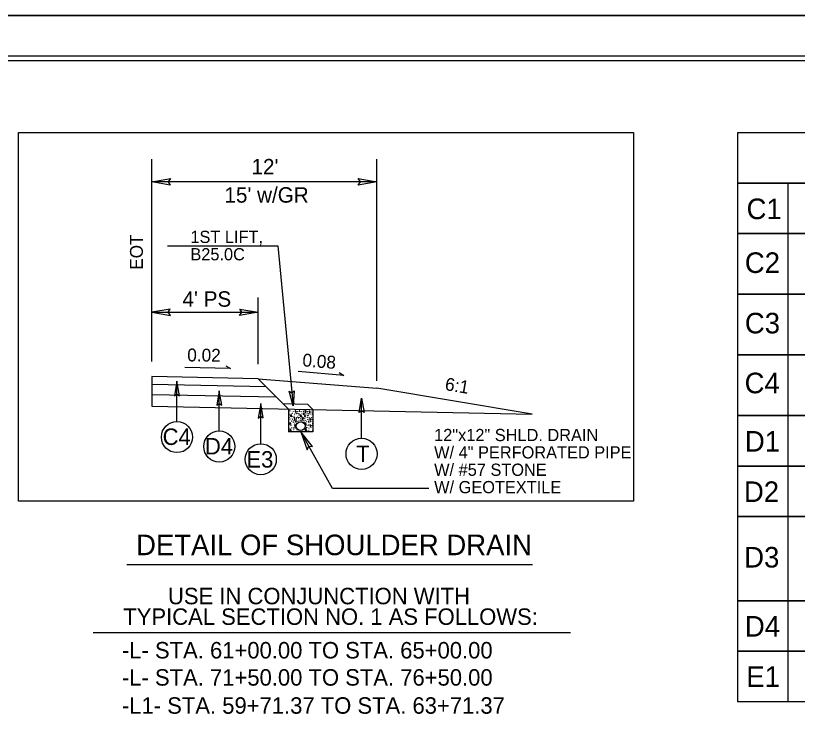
# Model space of a CAD drawing. Extents: x 573813 to 575363, y -54752 to -53123.
# Drawn here: x 574713.4 to 574799.8, y -53200.6 to -53122.8 of the extents above; entities that cross this region are included whole.
import ezdxf

# ---------------------------------------------------------------- set-up
doc = ezdxf.new("R2010")
doc.units = 0
for name, color, linetype in [('Old_Level_1', 7, 'Continuous'), ('Old_Level_11', 7, 'Continuous'), ('Old_Level_2', 7, 'Continuous'), ('Prop Pavement Schedule Description CELL', 7, 'Continuous'), ('Sheet Cutting Line CELL', 7, 'Continuous'), ('Sheet Plot Border Inside CELL', 7, 'Continuous'), ('Sheet Plot Border Outside CELL', 7, 'Continuous'), ('Sheet Typical CELL', 7, 'Continuous'), ('Typical Curb CELL', 7, 'Continuous'), ('Typical ID Circle CELL', 7, 'Continuous'), ('Typical Terminator CELL', 7, 'Continuous')]:
    doc.layers.add(name, color=color, linetype=linetype)

msp = doc.modelspace()

# ---------------------------------------------------------------- linework, layer by layer
at = {"layer": 'Old_Level_1'}
for p, q in [((574737.156, -53161.805), (574732.098, -53161.7)), ((574736.61, -53161.532), (574737.156, -53161.805)), ((574740.21, -53162.963), (574728.439, -53162.718)), ((574740.21, -53162.963), (574743.555, -53166.307)), ((574740.21, -53162.963), (574753.308, -53164.005)), ((574749.664, -53162.571), (574744.624, -53162.133)), ((574749.137, -53162.263), (574749.664, -53162.571)), ((574741.078, -53163.831), (574728.439, -53163.568)), ((574728.439, -53164.673), (574742.206, -53164.959)), ((574770.476, -53166.867), (574753.308, -53164.005)), ((574728.439, -53165.993), (574770.476, -53166.867)), ((574742.937, -53165.69), (574745.642, -53165.746)), ((574745.642, -53165.746), (574746.259, -53166.363))]:
    msp.add_line(p, q, dxfattribs=at)
at = {"layer": 'Old_Level_11'}
for p, q in [((574728.439, -53161.032), (574728.439, -53138.705)), ((574753.308, -53163.186), (574753.308, -53138.706)), ((574753.308, -53141.192), (574728.439, -53141.192)), ((574730.18, -53148.279), (574742.38, -53148.279)), ((574742.38, -53148.279), (574744.058, -53165.931)), ((574740.21, -53161.343), (574740.21, -53153.987)), ((574728.439, -53155.6), (574740.21, -53155.6)), ((574748.424, -53175.085), (574744.907, -53168.827)), ((574759.059, -53175.085), (574748.424, -53175.085)), ((574725.687, -53183.454), (574770.532, -53183.454)), ((574721.951, -53190.973), (574774.709, -53190.973))]:
    msp.add_line(p, q, dxfattribs=at)
for points in [[(574730.486, -53141.544), (574728.439, -53141.192), (574730.497, -53140.828), (574730.236, -53141.191)], [(574751.261, -53140.839), (574753.308, -53141.192), (574751.25, -53141.556), (574751.511, -53141.192)], [(574730.486, -53155.248), (574728.439, -53155.6), (574730.497, -53155.964), (574730.236, -53155.6)], [(574738.163, -53155.248), (574740.21, -53155.6), (574738.152, -53155.964), (574738.413, -53155.6)], [(574744.184, -53164.275), (574744.058, -53165.931), (574743.613, -53164.32), (574743.922, -53164.5)], [(574746.217, -53170.439), (574744.907, -53168.827), (574745.598, -53170.8), (574745.787, -53170.393)]]:
    msp.add_lwpolyline(points, close=True, dxfattribs=at)
at = {"layer": 'Old_Level_2'}
for p, q in [((574728.439, -53162.718), (574728.439, -53165.993)), ((574743.555, -53166.307), (574743.555, -53168.827)), ((574746.259, -53166.363), (574746.259, -53168.827)), ((574746.259, -53168.827), (574743.555, -53168.827))]:
    msp.add_line(p, q, dxfattribs=at)
msp.add_circle((574744.898, -53168.18), 0.485, dxfattribs=at)
at = {"layer": 'Prop Pavement Schedule Description CELL'}
for points in [[(574713.697, -53135.756), (574781.699, -53135.756), (574781.699, -53176.482), (574713.697, -53176.482)], [(574793.203, -53135.756), (574941.304, -53135.756), (574941.304, -53141.35), (574793.203, -53141.35)]]:
    msp.add_lwpolyline(points, close=True, dxfattribs=at)
for points in [[(574798.785, -53146.919), (574793.203, -53146.919), (574793.203, -53141.35), (574867.256, -53141.35), (574867.256, -53146.919), (574798.785, -53146.919), (574798.785, -53141.338)], [(574798.785, -53153.617), (574793.203, -53153.617), (574793.203, -53146.919), (574867.257, -53146.919), (574867.257, -53153.617), (574798.785, -53153.617), (574798.785, -53146.919)], [(574798.785, -53160.315), (574793.203, -53160.315), (574793.203, -53153.617), (574867.257, -53153.617), (574867.257, -53160.315), (574798.785, -53160.315), (574798.785, -53153.617)], [(574798.785, -53167.012), (574793.203, -53167.012), (574793.203, -53160.315), (574867.257, -53160.315), (574867.257, -53167.012), (574798.785, -53167.012), (574798.785, -53160.315)], [(574798.785, -53172.594), (574793.203, -53172.594), (574793.203, -53167.012), (574867.251, -53167.012), (574867.251, -53172.594), (574798.785, -53172.594), (574798.785, -53167.012)], [(574798.785, -53178.175), (574793.203, -53178.175), (574793.203, -53172.594), (574867.251, -53172.594), (574867.251, -53178.16), (574798.785, -53178.16), (574798.785, -53172.594)], [(574798.785, -53187.465), (574793.204, -53187.465), (574793.203, -53178.175), (574867.248, -53178.155), (574867.25, -53187.465), (574798.784, -53187.483), (574798.781, -53178.171)], [(574798.785, -53193.046), (574793.204, -53193.046), (574793.204, -53187.465), (574867.25, -53187.465), (574867.25, -53193.046), (574798.785, -53193.046), (574798.785, -53187.465)], [(574798.785, -53198.628), (574793.204, -53198.628), (574793.204, -53193.046), (574867.25, -53193.046), (574867.25, -53198.628), (574798.785, -53198.628), (574798.785, -53193.046)]]:
    msp.add_lwpolyline(points, dxfattribs=at)
at = {"layer": 'Sheet Cutting Line CELL'}
msp.add_line((574669.731, -53122.834), (575006.712, -53122.834), dxfattribs=at)
at = {"layer": 'Sheet Plot Border Inside CELL'}
msp.add_lwpolyline([(575005.811, -53127.327), (574672.332, -53127.327), (574672.332, -53338.46), (575005.811, -53338.46)], close=True, dxfattribs=at)
at = {"layer": 'Sheet Plot Border Outside CELL'}
msp.add_line((575006.712, -53122.834), (574669.731, -53122.834), dxfattribs=at)
msp.add_lwpolyline([(575006.712, -53122.834), (574669.731, -53122.834), (574669.731, -53342.952), (575006.712, -53342.952)], close=True, dxfattribs=at)
at = {"layer": 'Sheet Typical CELL'}
msp.add_lwpolyline([(575003.31, -53127.837), (574703.149, -53127.837), (574703.149, -53337.95), (575003.31, -53337.95)], close=True, dxfattribs=at)
at = {"layer": 'Typical Curb CELL'}
for p, q in [((574743.883, -53166.95), (574743.771, -53166.972)), ((574743.771, -53166.972), (574743.828, -53167.141)), ((574743.828, -53167.141), (574743.883, -53166.95)), ((574744.284, -53166.458), (574744.349, -53166.69)), ((574744.412, -53166.549), (574744.284, -53166.458)), ((574744.349, -53166.69), (574744.412, -53166.549)), ((574744.967, -53166.965), (574744.855, -53166.987)), ((574744.855, -53166.987), (574744.912, -53167.157)), ((574744.912, -53167.157), (574744.967, -53166.965)), ((574745.039, -53167.241), (574745.103, -53167.473)), ((574745.166, -53167.332), (574745.039, -53167.241)), ((574745.425, -53166.993), (574745.312, -53167.015)), ((574745.312, -53167.015), (574745.369, -53167.185)), ((574745.368, -53166.474), (574745.433, -53166.705)), ((574745.496, -53166.565), (574745.368, -53166.474)), ((574745.369, -53167.185), (574745.425, -53166.993)), ((574745.433, -53166.705), (574745.496, -53166.565)), ((574745.826, -53166.502), (574745.891, -53166.733)), ((574745.954, -53166.593), (574745.826, -53166.502)), ((574745.891, -53166.733), (574745.954, -53166.593)), ((574743.789, -53167.817), (574743.676, -53167.838)), ((574743.676, -53167.838), (574743.733, -53168.008)), ((574743.733, -53168.008), (574743.789, -53167.817)), ((574744.19, -53167.325), (574744.254, -53167.556)), ((574744.318, -53167.416), (574744.19, -53167.325)), ((574744.212, -53168.053), (574744.277, -53168.284)), ((574744.34, -53168.144), (574744.212, -53168.053)), ((574744.254, -53167.556), (574744.318, -53167.416)), ((574744.277, -53168.284), (574744.34, -53168.144)), ((574745.103, -53167.473), (574745.166, -53167.332)), ((574745.479, -53167.839), (574745.366, -53167.861)), ((574745.366, -53167.861), (574745.424, -53168.031)), ((574745.424, -53168.031), (574745.479, -53167.839)), ((574745.88, -53167.348), (574745.945, -53167.579)), ((574746.008, -53167.439), (574745.88, -53167.348)), ((574745.903, -53168.007), (574745.967, -53168.239)), ((574746.031, -53168.098), (574745.903, -53168.007)), ((574745.945, -53167.579), (574746.008, -53167.439)), ((574745.967, -53168.239), (574746.031, -53168.098)), ((574743.811, -53168.545), (574743.699, -53168.566)), ((574743.699, -53168.566), (574743.756, -53168.736)), ((574743.756, -53168.736), (574743.811, -53168.545)), ((574745.502, -53168.499), (574745.389, -53168.521)), ((574745.389, -53168.521), (574745.446, -53168.69)), ((574745.446, -53168.69), (574745.502, -53168.499))]:
    msp.add_line(p, q, dxfattribs=at)
for centre in [(574744.299, -53166.374), (574745.383, -53166.389), (574745.841, -53166.417), (574743.634, -53166.961), (574743.634, -53167.201), (574743.659, -53166.838), (574743.67, -53166.476), (574743.694, -53166.521), (574743.877, -53166.528), (574743.933, -53167.106), (574743.968, -53166.775), (574744.109, -53166.549), (574744.158, -53167.169), (574744.18, -53166.754), (574744.201, -53166.902), (574744.204, -53167.24), (574744.412, -53166.803), (574744.424, -53167.259), (574744.56, -53166.578), (574744.567, -53167.197), (574744.588, -53167.007), (574744.637, -53166.796), (574744.718, -53166.977), (574744.718, -53167.216), (574744.743, -53166.853), (574744.754, -53166.491), (574744.778, -53166.536), (574744.961, -53166.544), (574745.017, -53167.121), (574745.052, -53166.79), (574745.053, -53167.157), (574745.176, -53167.005), (574745.176, -53167.244), (574745.193, -53166.565), (574745.2, -53166.881), (574745.211, -53166.519), (574745.236, -53166.565), (574745.242, -53167.184), (574745.264, -53166.769), (574745.285, -53166.917), (574745.418, -53166.572), (574745.475, -53167.149), (574745.496, -53166.818), (574745.51, -53166.818), (574745.644, -53166.593), (574745.651, -53166.593), (574745.651, -53167.212), (574745.672, -53167.022), (574745.7, -53167.212), (574745.721, -53166.797), (574745.721, -53166.811), (574745.742, -53166.945), (574745.895, -53167.263), (574745.954, -53166.846), (574746.101, -53166.621), (574746.108, -53167.24), (574746.129, -53167.05), (574746.179, -53166.839), (574743.575, -53167.342), (574743.598, -53168.07), (574743.599, -53167.388), (574743.622, -53168.116), (574743.782, -53167.395), (574743.805, -53168.123), (574743.838, -53167.972), (574743.874, -53167.641), (574744.014, -53167.416), (574744.037, -53168.144), (574744.064, -53168.035), (574744.085, -53167.62), (574744.106, -53167.768), (574744.227, -53167.968), (574744.317, -53167.669), (574744.388, -53167.745), (574744.388, -53167.984), (574744.413, -53167.621), (574744.448, -53167.304), (574744.465, -53167.444), (574744.493, -53167.873), (574744.542, -53167.662), (574744.631, -53167.311), (574744.723, -53167.558), (574744.863, -53167.332), (574744.934, -53167.537), (574744.955, -53167.685), (574745.166, -53167.586), (574745.254, -53167.727), (574745.265, -53167.365), (574745.29, -53167.41), (574745.314, -53167.361), (574745.342, -53167.79), (574745.391, -53167.579), (574745.472, -53167.418), (574745.495, -53168.077), (574745.529, -53167.995), (574745.564, -53167.664), (574745.705, -53167.439), (574745.727, -53168.098), (574745.754, -53168.058), (574745.775, -53167.643), (574745.796, -53167.791), (574745.918, -53167.923), (574746.008, -53167.692), (574746.155, -53167.467), (574746.162, -53168.086), (574746.178, -53168.127), (574746.184, -53167.896), (574746.233, -53167.685), (574743.587, -53168.432), (574743.861, -53168.7), (574743.896, -53168.369), (574744.086, -53168.764), (574744.108, -53168.348), (574744.129, -53168.496), (574744.34, -53168.397), (574744.495, -53168.791), (574744.51, -53168.556), (574744.51, -53168.795), (574744.516, -53168.601), (574744.809, -53168.7), (574745.034, -53168.764), (574745.253, -53168.75), (574745.435, -53168.172), (574745.442, -53168.791), (574745.463, -53168.601), (574745.513, -53168.39), (574745.552, -53168.655), (574745.587, -53168.324), (574745.777, -53168.718), (574745.798, -53168.303), (574745.819, -53168.451), (574746.03, -53168.352), (574746.185, -53168.746), (574746.206, -53168.556)]:
    msp.add_circle(centre, 0.00989, dxfattribs=at)
at = {"layer": 'Typical ID Circle CELL'}
for p, q in [((574731.226, -53167.671), (574731.226, -53163.232)), ((574735.902, -53168.718), (574735.902, -53164.279)), ((574751.628, -53169.53), (574751.628, -53165.092)), ((574740.49, -53170.128), (574740.49, -53165.69))]:
    msp.add_line(p, q, dxfattribs=at)
for centre in [(574731.226, -53169.388), (574735.902, -53170.435), (574751.628, -53171.247), (574740.49, -53171.846)]:
    msp.add_circle(centre, 1.718, dxfattribs=at)
at = {"layer": 'Typical Terminator CELL'}
for points in [[(574731.5, -53164.822), (574731.226, -53163.232), (574730.943, -53164.831), (574731.226, -53164.628)], [(574736.176, -53165.869), (574735.902, -53164.279), (574735.619, -53165.878), (574735.902, -53165.675)], [(574751.354, -53166.682), (574751.628, -53165.092), (574751.911, -53166.691), (574751.628, -53166.488)], [(574740.763, -53167.28), (574740.49, -53165.69), (574740.207, -53167.289), (574740.49, -53167.086)]]:
    msp.add_lwpolyline(points, close=True, dxfattribs=at)

# ---------------------------------------------------------------- texts
at = {"layer": 'Old_Level_1'}
for s, height, rotation, p in [('EOT', 1.4212, 89.99944, (574727.454, -53150.914)), ('0.02', 1.4212, 359.39371, (574732.358, -53161.028)), ('0.08', 1.4212, 355.3327, (574745.051, -53161.57)), ('6:1', 1.4212, 350.53764, (574760.775, -53164.191)), ('DETAIL OF SHOULDER DRAIN', 2.27395, 359.99996, (574726.704, -53182.439)), ('USE IN CONJUNCTION WITH', 1.81916, 359.99996, (574730.233, -53187.864)), ('TYPICAL SECTION NO. 1 AS FOLLOWS:', 1.81916, 359.99996, (574725.292, -53190.138)), ('-L- STA. 61+00.00 TO STA. 65+00.00', 1.81916, 0, (574725.144, -53193.849)), ('-L- STA. 71+50.00 TO STA. 76+50.00', 1.81916, 0, (574725.144, -53196.852)), ('-L1- STA. 59+71.37 TO STA. 63+71.37', 1.81916, 0, (574725.144, -53199.956))]:
    msp.add_text(s, height=height, rotation=rotation, dxfattribs=at).set_placement(p)
for s, p in [('C3', (574793.997, -53157.94)), ('C4', (574793.97, -53164.551))]:
    msp.add_text(s, height=2.2739, dxfattribs=at).set_placement(p)
at = {"layer": 'Old_Level_11'}
for s, height, rotation, p in [("12'", 1.7055, 0.00015, (574739.465, -53140.368)), ("15' w/GR", 1.7055, 0.00015, (574736.476, -53143.494)), ('1ST LIFT,', 1.3502, 359.99996, (574732.71, -53147.95)), ('B25.0C', 1.3502, 359.99996, (574732.71, -53149.868)), ("4' PS", 1.7055, 0.00181, (574731.84, -53154.99)), ('12"x12" SHLD. DRAIN', 1.35016, 359.99996, (574759.651, -53169.838)), ('W/ 4" PERFORATED PIPE', 1.35016, 359.99996, (574759.651, -53171.756)), ('W/ #57 STONE', 1.35016, 359.99996, (574759.651, -53173.675)), ('W/ GEOTEXTILE', 1.35016, 359.99996, (574759.651, -53175.594))]:
    msp.add_text(s, height=height, rotation=rotation, dxfattribs=at).set_placement(p)
at = {"layer": 'Prop Pavement Schedule Description CELL'}
for s, height, p in [('C1', 2.2739, (574794.187, -53145.316)), ('C2', 2.2739, (574793.994, -53151.261)), ('C4', 1.8192, (574729.642, -53170.263)), ('D1', 2.2739, (574794, -53170.998)), ('D4', 1.8192, (574734.318, -53171.31)), ('E3', 1.8192, (574738.902, -53172.765)), ('D2', 2.2739, (574793.893, -53176.565)), ('D3', 2.2739, (574793.921, -53183.802)), ('D4', 2.2739, (574794, -53191.432)), ('E1', 2.2739, (574794.152, -53196.989))]:
    msp.add_text(s, height=height, dxfattribs=at).set_placement(p)
msp.add_text('T', height=1.819, rotation=360, dxfattribs=at).set_placement((574751.03, -53172.157))

doc.saveas('drawing.dxf')
